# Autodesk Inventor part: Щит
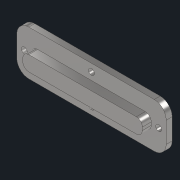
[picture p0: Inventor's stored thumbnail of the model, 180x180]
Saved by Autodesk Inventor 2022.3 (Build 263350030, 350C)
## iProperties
Created: 2022-08
Part Number: Щит
Material: Сталь 40ХНМА
Document SubType Name: Modeling
Designer: Карташов
Density: 7.85 g/cm^3
Appearance: С умеренной полировкой
Author: Карташов
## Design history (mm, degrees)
sketch "Эскиз1"
  geometry: L1 (-21, -7.5)-(21, -7.5); L2 (25, -3.5)-(25, 3.5); L3 (21, 7.5)-(-21, 7.5); L4 (-25, 3.5)-(-25, -3.5); L5 (-25, -7.5)-(25, 7.5); L6 (25, -7.5)-(-25, 7.5); L7 (-18, -2.5)-(18, -2.5); L8 (20, -0.5)-(20, 0.5); L9 (18, 2.5)-(-18, 2.5); L10 (-20, 0.5)-(-20, -0.5); L11 (-20, -2.5)-(20, 2.5); L12 (20, -2.5)-(-20, 2.5); A1 r 4 centre (21, 3.5) between (25, 3.5) and (21, 7.5); A2 r 4 centre (21, -3.5) between (21, -7.5) and (25, -3.5); A3 r 4 centre (-21, -3.5) between (-25, -3.5) and (-21, -7.5); A4 r 4 centre (-21, 3.5) between (-21, 7.5) and (-25, 3.5); A5 r 2 centre (-18, 0.5) between (-18, 2.5) and (-20, 0.5); A6 r 2 centre (18, 0.5) between (20, 0.5) and (18, 2.5); A7 r 2 centre (18, -0.5) between (18, -2.5) and (20, -0.5); A8 r 2 centre (-18, -0.5) between (-20, -0.5) and (-18, -2.5); 1 further point
  constraints: 24 end point, 16 point on circle, 16 point on line, 16 tangent, 8 centre point, 6 equal radius, 4 midpoint, 4 parallel, 2 horizontal, 2 perpendicular
  dimensions: "d0" = 50 distance of L6.end L5.end; "d1" = 15 distance of L5.end L6.start; "d2" = 40 distance of L12.end L11.end; "d3" = 5 distance of L11.end L12.start; "d4" = 4 radius of A1; "d5" = 2 radius of A5
extrude "Выдавливание1" new body sketch "Эскиз1" distance "d6" = 2; taper "d7" = 0 deg
extrude "Выдавливание2" join sketch "Эскиз1" distance "d8" = 5; taper "d9" = 0 deg
sketch "Эскиз2"
  geometry: L1 (25, -3.5)-(25, 3.5) reference; L2 (21, 7.5)-(-21, 7.5) reference; L3 (-25, 3.5)-(-25, -3.5) reference; L4 (-21, -7.5)-(21, -7.5) reference; L5 (-20, -0.5)-(-20, 0.5) reference; L6 (-18, 2.5)-(18, 2.5) reference; L7 (20, 0.5)-(20, -0.5) reference; L8 (18, -2.5)-(-18, -2.5) reference; A1 r 4 centre (21, -3.5) between (21, -7.5) and (25, -3.5) reference; A2 r 4 centre (21, 3.5) between (25, 3.5) and (21, 7.5) reference; A3 r 4 centre (-21, 3.5) between (-21, 7.5) and (-25, 3.5) reference; A4 r 4 centre (-21, -3.5) between (-25, -3.5) and (-21, -7.5) reference; A5 r 2 centre (-18, -0.5) between (-20, -0.5) and (-18, -2.5) reference; A6 r 2 centre (-18, 0.5) between (-18, 2.5) and (-20, 0.5) reference; A7 r 2 centre (18, 0.5) between (20, 0.5) and (18, 2.5) reference; A8 r 2 centre (18, -0.5) between (18, -2.5) and (20, -0.5) reference; 5 further points
  constraints: 2 midpoint, 1 horizontal alignment, 1 vertical alignment
  dimensions: "d10" = 22.5 distance of point (0, 0) point (-22.5, 0); "d11" = 5 distance of point (0, 0) point (0, 5)
hole "Отверстие1" sketch "Эскиз2" at (-22.5, 0), (0, 5) diameter "d12" = 1; stored, may be unused: countersink angle "d16" = 90 deg, drill point angle "d18" = 0 deg; dims "d13" = 6, "d14" = 2, "d15" = 2, "d17" = 22.5
mirror "Зеркальное отражение1"
mirror "Зеркальное отражение2"
node "Твердое тело1"
node "Спроецированная петля1"
